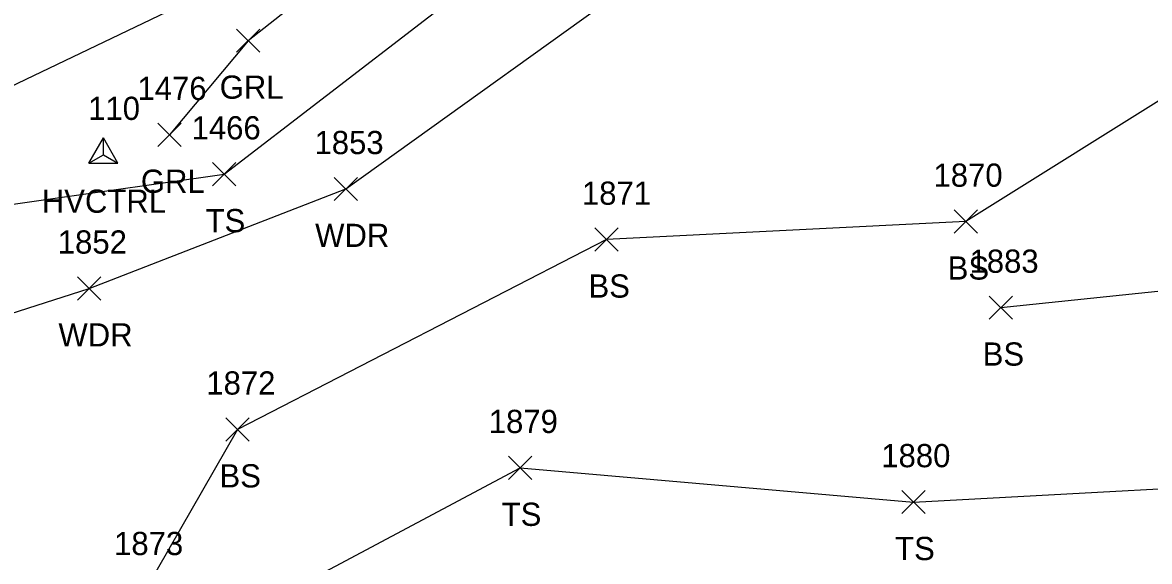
# Model space of a CAD drawing. Extents: x 1633660 to 1636532, y 388643 to 392631.
# Drawn here: x 1634396.6 to 1634493.7, y 388865.4 to 388911.8 of the extents above; entities that cross this region are included whole.
import ezdxf

# ---------------------------------------------------------------- set-up
doc = ezdxf.new("R2010")
doc.units = 0
for name, color, linetype in [('C_A', 7, 'Continuous'), ('C_I', 7, 'Continuous'), ('CPSM', 7, 'Continuous'), ('L_A', 7, 'Continuous'), ('L_I', 7, 'Continuous'), ('L_TIC', 7, 'Continuous'), ('LAWA', 7, 'Continuous'), ('LELB', 7, 'Continuous'), ('PET', 7, 'Continuous'), ('R_A', 7, 'Continuous'), ('R_I', 7, 'Continuous'), ('R_TIC', 7, 'Continuous'), ('RGR', 7, 'Continuous')]:
    doc.layers.add(name, color=color, linetype=linetype)

msp = doc.modelspace()

# ---------------------------------------------------------------- linework, layer by layer
at = {"layer": 'CPSM'}
for p, q in [((1634402.356, 388899.68), (1634403.606, 388901.845)), ((1634404.856, 388899.68), (1634403.606, 388901.845)), ((1634403.606, 388900.401), (1634403.606, 388901.845)), ((1634402.356, 388899.68), (1634403.606, 388900.401)), ((1634403.606, 388900.401), (1634403.606, 388900.401)), ((1634403.606, 388900.401), (1634404.856, 388899.68)), ((1634402.356, 388899.68), (1634404.856, 388899.68))]:
    msp.add_line(p, q, dxfattribs=at)
at = {"layer": 'L_TIC'}
for points in [[(1634412.992, 388897.724), (1634414.992, 388899.724)], [(1634414.992, 388897.724), (1634412.992, 388899.724)], [(1634423.472, 388896.455), (1634425.472, 388898.455)], [(1634425.472, 388896.455), (1634423.472, 388898.455)], [(1634476.85, 388893.646), (1634478.85, 388895.646)], [(1634478.85, 388893.646), (1634476.85, 388895.646)], [(1634445.927, 388892.092), (1634447.927, 388894.092)], [(1634447.927, 388892.092), (1634445.927, 388894.092)], [(1634401.37, 388887.883), (1634403.37, 388889.883)], [(1634403.37, 388887.883), (1634401.37, 388889.883)], [(1634479.864, 388886.231), (1634481.864, 388888.231)], [(1634481.864, 388886.231), (1634479.864, 388888.231)], [(1634414.158, 388875.737), (1634416.158, 388877.737)], [(1634416.158, 388875.737), (1634414.158, 388877.737)], [(1634438.484, 388872.424), (1634440.484, 388874.424)], [(1634440.484, 388872.424), (1634438.484, 388874.424)], [(1634472.355, 388869.478), (1634474.355, 388871.478)], [(1634474.355, 388869.478), (1634472.355, 388871.478)]]:
    msp.add_lwpolyline(points, dxfattribs=at)
at = {"layer": 'LAWA'}
msp.add_lwpolyline([(1634130.811, 388762.968), (1634125.77, 388773.71), (1634128.727, 388780.906), (1634147.798, 388788.83), (1634164.313, 388795.201), (1634191.325, 388807.234), (1634212.876, 388815.093), (1634244.473, 388827.565), (1634270.045, 388838.562), (1634299.492, 388850.564), (1634310.774, 388855.38), (1634327.207, 388862.061), (1634379.707, 388881.611), (1634402.37, 388888.883), (1634424.472, 388897.455), (1634452.158, 388917.363), (1634475.032, 388932.291), (1634483.739, 388944.664)], dxfattribs=at)
at = {"layer": 'LELB'}
for points in [[(1634125.579, 388742.686), (1634122.377, 388746.523), (1634122.379, 388759.174), (1634119.847, 388773.411), (1634127.606, 388794.705), (1634159.932, 388808.1), (1634199.649, 388823.276), (1634240.013, 388839.132), (1634282.637, 388856.778), (1634322.867, 388872.904), (1634357.402, 388883.596), (1634392.968, 388895.749), (1634413.992, 388898.724), (1634440.42, 388919.1), (1634461.601, 388936.25), (1634480.462, 388947.827), (1634480.68, 388954.277)], [(1634584.894, 388915.403), (1634565.239, 388902.907), (1634528.637, 388898.734), (1634496.984, 388906.617), (1634477.85, 388894.646), (1634446.927, 388893.092), (1634415.158, 388876.737), (1634407.217, 388862.907), (1634384.253, 388848.396), (1634365.184, 388835.861)], [(1634366.11, 388829.226), (1634392.919, 388840.96), (1634414.747, 388860.236), (1634439.484, 388873.424), (1634473.355, 388870.478), (1634511.372, 388872.55), (1634556.169, 388880.749), (1634584.637, 388898.017), (1634601.642, 388909.043)], [(1634480.864, 388887.231), (1634505.418, 388889.787), (1634536.903, 388882.946)]]:
    msp.add_lwpolyline(points, dxfattribs=at)
at = {"layer": 'PET'}
msp.add_lwpolyline([(1634182.589, 388846.73), (1634235.607, 388867.857), (1634289.807, 388889.547), (1634340.226, 388910.316), (1634383.943, 388928.36), (1634416.956, 388942.424), (1634441.986, 388954.985), (1634450.019, 388959.853), (1634465.24, 388958.085), (1634480.348, 388956.008), (1634458.413, 388940.869), (1634427.909, 388921.751), (1634384.731, 388901.048), (1634334.49, 388879.365), (1634279.866, 388857.153), (1634233.656, 388838.288), (1634176.136, 388816.11)], dxfattribs=at)
at = {"layer": 'R_TIC'}
for points in [[(1634415.071, 388909.226), (1634417.071, 388911.226)], [(1634417.071, 388909.226), (1634415.071, 388911.226)], [(1634408.286, 388901.118), (1634410.286, 388903.118)], [(1634410.286, 388901.118), (1634408.286, 388903.118)]]:
    msp.add_lwpolyline(points, dxfattribs=at)
at = {"layer": 'RGR'}
msp.add_lwpolyline([(1634480.3, 388955.361), (1634459.19, 388940.913), (1634428.243, 388919.846), (1634416.071, 388910.226), (1634409.286, 388902.118)], dxfattribs=at)

# ---------------------------------------------------------------- texts
at = {"layer": 'C_A'}
msp.add_text('HVCTRL', height=2, dxfattribs=at).set_placement((1634398.299, 388895.401))
at = {"layer": 'C_I'}
msp.add_text('110', height=2, dxfattribs=at).set_placement((1634402.291, 388903.401))
at = {"layer": 'L_A'}
for s, p in [('TS', (1634412.402, 388893.724)), ('WDR', (1634421.834, 388892.455)), ('BS', (1634476.291, 388889.646)), ('BS', (1634445.368, 388888.092)), ('WDR', (1634399.732, 388883.883)), ('BS', (1634479.305, 388882.231)), ('BS', (1634413.599, 388871.737)), ('TS', (1634437.894, 388868.424)), ('TS', (1634471.765, 388865.478))]:
    msp.add_text(s, height=2, dxfattribs=at).set_placement(p)
at = {"layer": 'L_I'}
for s, p in [('1466', (1634411.197, 388901.724)), ('1853', (1634421.779, 388900.455)), ('1870', (1634475.07, 388897.646)), ('1871', (1634444.801, 388896.092)), ('1852', (1634399.677, 388891.883)), ('1883', (1634478.171, 388890.231)), ('1872', (1634412.465, 388879.737)), ('1879', (1634436.783, 388876.424)), ('1880', (1634470.576, 388873.478)), ('1873', (1634404.524, 388865.907))]:
    msp.add_text(s, height=2, dxfattribs=at).set_placement(p)
at = {"layer": 'R_A'}
for p in [(1634413.615, 388905.226), (1634406.83, 388897.118)]:
    msp.add_text('GRL', height=2, dxfattribs=at).set_placement(p)
at = {"layer": 'R_I'}
msp.add_text('1476', height=2, dxfattribs=at).set_placement((1634406.538, 388905.118))

doc.saveas('drawing.dxf')
